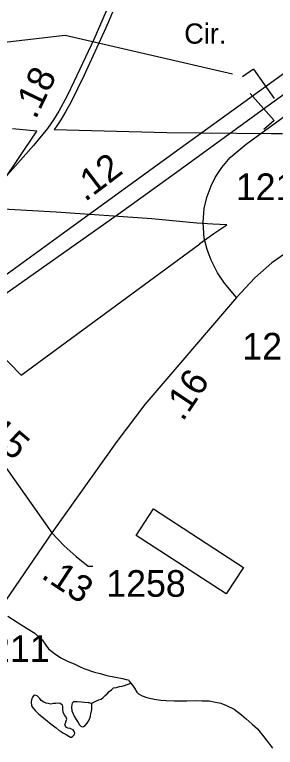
# Model space of a CAD drawing. Extents: x 2082433 to 2279600, y 546599 to 755198.
# Drawn here: x 2138630 to 2139852, y 591331 to 594769 of the extents above; entities that cross this region are included whole.
import ezdxf

# ---------------------------------------------------------------- set-up
doc = ezdxf.new("R2010")
doc.units = 0
for name, color, linetype in [('Exist Boundary Political City Limit New', 7, 'Continuous'), ('Exist Cultural Manufacturing Building Footprint', 7, 'Continuous'), ('Exist Hydrographic Misc Water Feature', 7, 'Continuous'), ('Exist Road Non-System Type 51 Label', 7, 'Continuous'), ('Exist Road Primary Interstate Divided Center Attributed', 7, 'Continuous'), ('Exist Road Primary Interstate Mileage Hundredths English Label', 7, 'Continuous'), ('Exist Road Primary Interstate Structure Cantilever Sign CELL', 7, 'Continuous'), ('Exist Road Primary Interstate Structure Cantilever Sign Number Label', 7, 'Continuous'), ('Exist Road Primary US Service Attributed', 7, 'Continuous'), ('Exist Road Secondary Mileage Hundredths English Label', 7, 'Continuous'), ('Exist Road Secondary Type 51 Attributed', 7, 'Continuous'), ('Exist Road Secondary Type 51 Number Label', 7, 'Continuous'), ('Map Preparation Boundary City Limit Buffer Line', 7, 'Continuous')]:
    doc.layers.add(name, color=color, linetype=linetype)

msp = doc.modelspace()

# ---------------------------------------------------------------- linework, layer by layer
at = {"layer": 'Exist Boundary Political City Limit New'}
for points in [[(2139088.2, 594781), (2139073.2, 594743.8), (2139057, 594706.6), (2138955.2, 594485.7), (2138892.5, 594356.4), (2138868.8, 594312.4), (2138847, 594275.9), (2138824.8, 594242), (2138815.5, 594229.6), (2138989.5, 594225), (2139342.5, 594215.7), (2139831.8, 594210.8), (2139885.8, 594211)], [(2138490, 593251.3), (2138660.2, 593077.1), (2139497.8, 593694.2), (2139497.5, 593695.9), (2139563.5, 593742.8), (2139624.8, 593783), (2139559, 593786.1), (2139483.5, 593791.2), (2139272.2, 593810.6), (2138825, 593842.1), (2138490.5, 593860.6), (2138733.5, 594222.1), (2138619.2, 594233.8)]]:
    msp.add_lwpolyline(points, dxfattribs=at)
at = {"layer": 'Exist Cultural Manufacturing Building Footprint'}
msp.add_lwpolyline([(2139199.4, 592325.6), (2139280.5, 592450.1), (2139701.9, 592175.6), (2139620.8, 592051.1)], close=True, dxfattribs=at)
at = {"layer": 'Exist Hydrographic Misc Water Feature'}
for points in [[(2138598.3, 591946.6), (2138642, 591918.5), (2138688.5, 591888.7), (2138724.4, 591867.1), (2138740, 591851.3), (2138758.6, 591835.1), (2138776.3, 591811.4), (2138788.6, 591793.3)], [(2138788.6, 591793.3), (2138816.5, 591771.6), (2138846.6, 591751.2), (2138876.8, 591735.4), (2138912.2, 591721.5), (2138934.4, 591711.2), (2138954.9, 591701.3), (2139004.5, 591683.6), (2139030.7, 591677.6), (2139062.7, 591667.9), (2139102.7, 591660.2), (2139134.9, 591654.2), (2139153, 591650.2), (2139162.8, 591648.3), (2139166.9, 591642.4), (2139174.5, 591632.3)], [(2138989.1, 591537.5), (2139001.2, 591543.8), (2139013.3, 591549.6), (2139025, 591553.9), (2139035.5, 591557.6), (2139045.3, 591565.9), (2139053.5, 591574), (2139062.9, 591581.9), (2139073, 591593.8), (2139083.2, 591601.9), (2139093.1, 591610.2), (2139107, 591612.1), (2139120.8, 591616.1), (2139133.1, 591618.3), (2139144.8, 591622.2), (2139174.5, 591632.3)], [(2139174.5, 591632.3), (2139184.9, 591618.2), (2139190.9, 591608.3), (2139202.8, 591590.3), (2139211, 591582.6), (2139227, 591572.5), (2139249.1, 591564.6), (2139283.2, 591556.7), (2139315.2, 591553.1), (2139339.6, 591551), (2139378.7, 591549.5), (2139437.6, 591549.6), (2139483.3, 591551.6), (2139508.9, 591549.7), (2139540.9, 591550.1), (2139570.9, 591544), (2139597.1, 591538.4), (2139623.6, 591528.3), (2139659.2, 591510.4), (2139693.1, 591484.5), (2139715.8, 591464.9), (2139743.7, 591440.8), (2139767.7, 591418.9), (2139797.8, 591381.1), (2139819.6, 591353.1), (2139838.2, 591327.1)], [(2138773.8, 591462.6), (2138801.7, 591440.9), (2138812, 591432.9), (2138824.3, 591422.9), (2138838, 591411.1), (2138848, 591405.1), (2138856, 591399.1), (2138872, 591391), (2138883.9, 591383.1), (2138891.7, 591379), (2138896, 591379.2), (2138901.8, 591383.2), (2138910, 591391.3), (2138912.2, 591397.4), (2138908.1, 591405.4), (2138903.8, 591413.3), (2138896, 591417.3), (2138889.9, 591419.1), (2138879.6, 591421), (2138873.5, 591425.2), (2138867.7, 591431), (2138865.7, 591439), (2138867.9, 591445.1), (2138871.6, 591455.1), (2138873.9, 591463.3), (2138871.6, 591472.9), (2138865.5, 591481.2), (2138859.3, 591491), (2138857.5, 591497), (2138855.4, 591511.1), (2138855.4, 591522.8), (2138853.4, 591528.8), (2138849.5, 591533.1), (2138843.7, 591536.8), (2138833.3, 591538.8), (2138823.2, 591537), (2138811.3, 591536.8), (2138799.4, 591534.6), (2138787.6, 591536.8), (2138777.7, 591538.7), (2138767.3, 591542.7), (2138754.9, 591550.6), (2138747.4, 591560.7), (2138741, 591566.5), (2138735.3, 591572.6), (2138725.2, 591576.6), (2138719.5, 591574.2), (2138713.3, 591566.2), (2138709.2, 591554.2), (2138707.6, 591544.3), (2138709.2, 591526.3), (2138715.8, 591516.4), (2138725.6, 591504.4), (2138735.5, 591494.4), (2138741.2, 591488.6), (2138773.8, 591462.6)], [(2138989.1, 591537.5), (2138981.3, 591539.5), (2138975, 591539.6), (2138957.5, 591541.5), (2138943.4, 591543.2), (2138923.3, 591545.4), (2138911.4, 591545.2), (2138905.5, 591545.3), (2138899.3, 591539.3), (2138897.5, 591533.1), (2138895.6, 591519.2), (2138897.5, 591503.1), (2138903.4, 591489.2), (2138909.6, 591475.3), (2138917.8, 591461.5), (2138927.8, 591447.4), (2138933.8, 591437.2), (2138939.5, 591431.4), (2138945.6, 591427.3), (2138952, 591429.5), (2138960, 591433.6), (2138970, 591445.5), (2138978, 591457.7), (2138983.6, 591471.4), (2138985.4, 591479.7), (2138987.5, 591489.4), (2138991.8, 591509.5), (2138991.6, 591521.7), (2138991, 591533.5), (2138989.1, 591537.5)]]:
    msp.add_lwpolyline(points, dxfattribs=at)
at = {"layer": 'Exist Road Primary Interstate Divided Center Attributed'}
for points in [[(2141492.5, 595646.6), (2141033.7, 595316.8), (2140441.4, 594889.6), (2139862.1, 594471.1), (2139406, 594141.3), (2139149.8, 593954.2), (2138875.6, 593755.6), (2138445.5, 593443.1), (2138258.4, 593312.4)], [(2138372.3, 593307.1), (2138555.2, 593438.2), (2139137.4, 593849.3), (2139406, 594042.9), (2139790.7, 594323), (2140205.8, 594622.5), (2140462, 594806.4), (2140982.9, 595188.1)]]:
    msp.add_lwpolyline(points, dxfattribs=at)
at = {"layer": 'Exist Road Primary Interstate Structure Cantilever Sign CELL'}
for p, q in [((2139750.1, 594513.6), (2139698.2, 594477.2)), ((2139750.1, 594513.6), (2139846.8, 594375.5)), ((2139845.6, 594273), (2139733.1, 594398.6)), ((2139845.6, 594273), (2139798.3, 594230.7))]:
    msp.add_line(p, q, dxfattribs=at)
at = {"layer": 'Exist Road Primary Interstate Structure Cantilever Sign Number Label'}
msp.add_lwpolyline([(2139650.7, 594489.7), (2138866, 594671.3), (2138243.4, 594600)], dxfattribs=at)
at = {"layer": 'Exist Road Primary US Service Attributed'}
msp.add_lwpolyline([(2139670.2, 593441.7), (2139613, 593509.8), (2139580.5, 593557.4), (2139550.3, 593616.9), (2139533, 593667.7), (2139518.9, 593720.7), (2139513, 593793.1), (2139518.4, 593861.2), (2139532.4, 593915.3), (2139550.8, 593966.1), (2139569.2, 594005.1), (2139600.5, 594052.6), (2139640.5, 594099.1), (2139715.1, 594161.9), (2140249.6, 594550.1), (2140899.6, 595011), (2141542.3, 595484.9), (2141620.6, 595537.9), (2141664.9, 595556.3), (2141846.5, 595603.3), (2142155.6, 595655.2)], dxfattribs=at)
at = {"layer": 'Exist Road Secondary Type 51 Attributed'}
for points in [[(2139058.2, 594785.2), (2139000.9, 594652.7), (2138909.3, 594456.8), (2138876.1, 594388.3), (2138837.4, 594315.9), (2138811.9, 594275), (2138783.8, 594235.5), (2138717.6, 594155.4), (2138572.9, 593991.6)], [(2139937.7, 593675.2), (2139836.1, 593603.9), (2139755.4, 593534.9), (2139670.2, 593441.7)], [(2139670.2, 593441.7), (2139239.5, 592939.9), (2139108.8, 592766.1), (2138804.8, 592337.8)], [(2138280.9, 593080), (2138549.5, 592696.8), (2138804.8, 592337.8)], [(2138804.8, 592337.8), (2138240, 591513.9)], [(2138804.8, 592337.8), (2138861.2, 592276.5), (2138917.7, 592227.3), (2138974.1, 592181.3), (2138996.3, 592181.3)]]:
    msp.add_lwpolyline(points, dxfattribs=at)
at = {"layer": 'Map Preparation Boundary City Limit Buffer Line'}
for points in [[(2139088.2, 594781), (2139073.2, 594743.8), (2139057, 594706.6), (2138955.2, 594485.7), (2138892.5, 594356.4), (2138868.8, 594312.4), (2138847, 594275.9), (2138824.8, 594242), (2138815.5, 594229.6), (2138989.5, 594225), (2139342.5, 594215.7), (2139831.8, 594210.8), (2139885.8, 594211)], [(2138490, 593251.3), (2138660.2, 593077.1), (2139497.8, 593694.2), (2139497.5, 593695.9), (2139563.5, 593742.8), (2139624.8, 593783), (2139559, 593786.1), (2139483.5, 593791.2), (2139272.2, 593810.6), (2138825, 593842.1), (2138490.5, 593860.6), (2138733.5, 594222.1), (2138619.2, 594233.8)]]:
    msp.add_lwpolyline(points, dxfattribs=at)

# ---------------------------------------------------------------- texts
at = {"layer": 'Exist Road Non-System Type 51 Label'}
msp.add_text('Cir.', height=95, dxfattribs=at).set_placement((2139424.9, 594632.7))
at = {"layer": 'Exist Road Primary Interstate Mileage Hundredths English Label'}
msp.add_text('.12', height=125, rotation=37.2587, dxfattribs=at).set_placement((2138960.1, 593888.4))
at = {"layer": 'Exist Road Secondary Mileage Hundredths English Label'}
for s, rotation, p in [('.18', 64.359, (2138728.3, 594274.4)), ('.16', 56.331, (2139418.2, 592856.5)), ('.15', 319.4815, (2138454.1, 592824.4)), ('.13', 326.7707, (2138749, 592129))]:
    msp.add_text(s, height=125, rotation=rotation, dxfattribs=at).set_placement(p)
at = {"layer": 'Exist Road Secondary Type 51 Number Label'}
for s, p in [('1219', (2139666.8, 593899)), ('1211', (2139697.3, 593150.9)), ('1258', (2139059.7, 592037.8)), ('1211', (2138421.8, 591731.8))]:
    msp.add_text(s, height=125, dxfattribs=at).set_placement(p)

doc.saveas('drawing.dxf')
